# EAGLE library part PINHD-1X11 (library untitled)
PIN HEADER
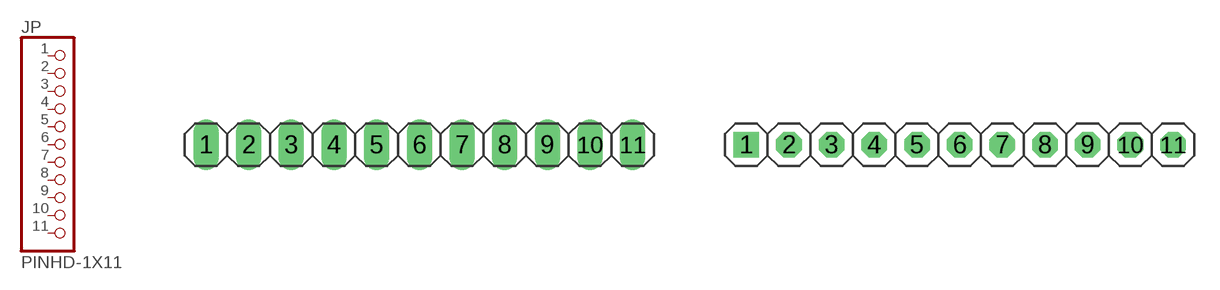
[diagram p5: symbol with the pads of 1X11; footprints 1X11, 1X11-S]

Designator prefix JP

## PINHD-1X11_2.54  [1X11]
1  1  pas
2  2  pas
3  3  pas
4  4  pas
5  5  pas
6  6  pas
7  7  pas
8  8  pas
9  9  pas
10  10  pas
11  11  pas

## PINHD-1X11_2.54-S  [1X11-S]
Pads as for 1X11

## PINHD-1X11_2.54-90°  [1X11/90]
Pads as for 1X11

## PINHD-1X11_2.54-90°-S  [1X11/90-S]
Pads as for 1X11

## PINHD-1X11_2.00  [1X11M]
Pads as for 1X11

## PINHD-1X11_2.54-SMD  [1X11SMD]
Pads as for 1X11

## PINHD-1X11_2.54-SMD-90°  [1X11SMD/90]
Pads as for 1X11

## Footprint 1X11 (pad centres in mm)
PIN HEADER - 2.54
drill 1.016 long: 1 -12.7,0; 2 -10.16,0; 3 -7.62,0; 4 -5.08,0; 5 -2.54,0; 6 0,0; 7 2.54,0; 8 5.08,0; 9 7.62,0; 10 10.16,0; 11 12.7,0

## Footprint 1X11-S (pad centres in mm)
PIN HEADER - 2.54
drill 1.016 square: 1 -12.7,0
drill 1.016 octagon: 2 -10.16,0; 3 -7.62,0; 4 -5.08,0; 5 -2.54,0; 6 0,0; 7 2.54,0; 8 5.08,0; 9 7.62,0; 10 10.16,0; 11 12.7,0

## Footprint 1X11/90 (pad centres in mm)
PIN HEADER - 2.54 90°
drill 1.016 long: 1 -12.7,-3.81; 2 -10.16,-3.81; 3 -7.62,-3.81; 4 -5.08,-3.81; 5 -2.54,-3.81; 6 0,-3.81; 7 2.54,-3.81; 8 5.08,-3.81; 9 7.62,-3.81; 10 10.16,-3.81; 11 12.7,-3.81

## Footprint 1X11/90-S (pad centres in mm)
PIN HEADER - 2.54 90°
drill 1.016 square: 1 -12.7,-3.81
drill 1.016 octagon: 2 -10.16,-3.81; 3 -7.62,-3.81; 4 -5.08,-3.81; 5 -2.54,-3.81; 6 0,-3.81; 7 2.54,-3.81; 8 5.08,-3.81; 9 7.62,-3.81; 10 10.16,-3.81; 11 12.7,-3.81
